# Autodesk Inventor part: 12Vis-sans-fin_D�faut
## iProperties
Created: 2011-01
Part Number: 12Vis-sans-fin_D�faut
Document SubType Name: Modeling
Designer: eric
Density: 1 g/cm^3
Mass: 7.07856 g
Surface Area: 44.7397 cm^2
Volume: 7.07856 cm^3
Author: eric
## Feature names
1. Base1
